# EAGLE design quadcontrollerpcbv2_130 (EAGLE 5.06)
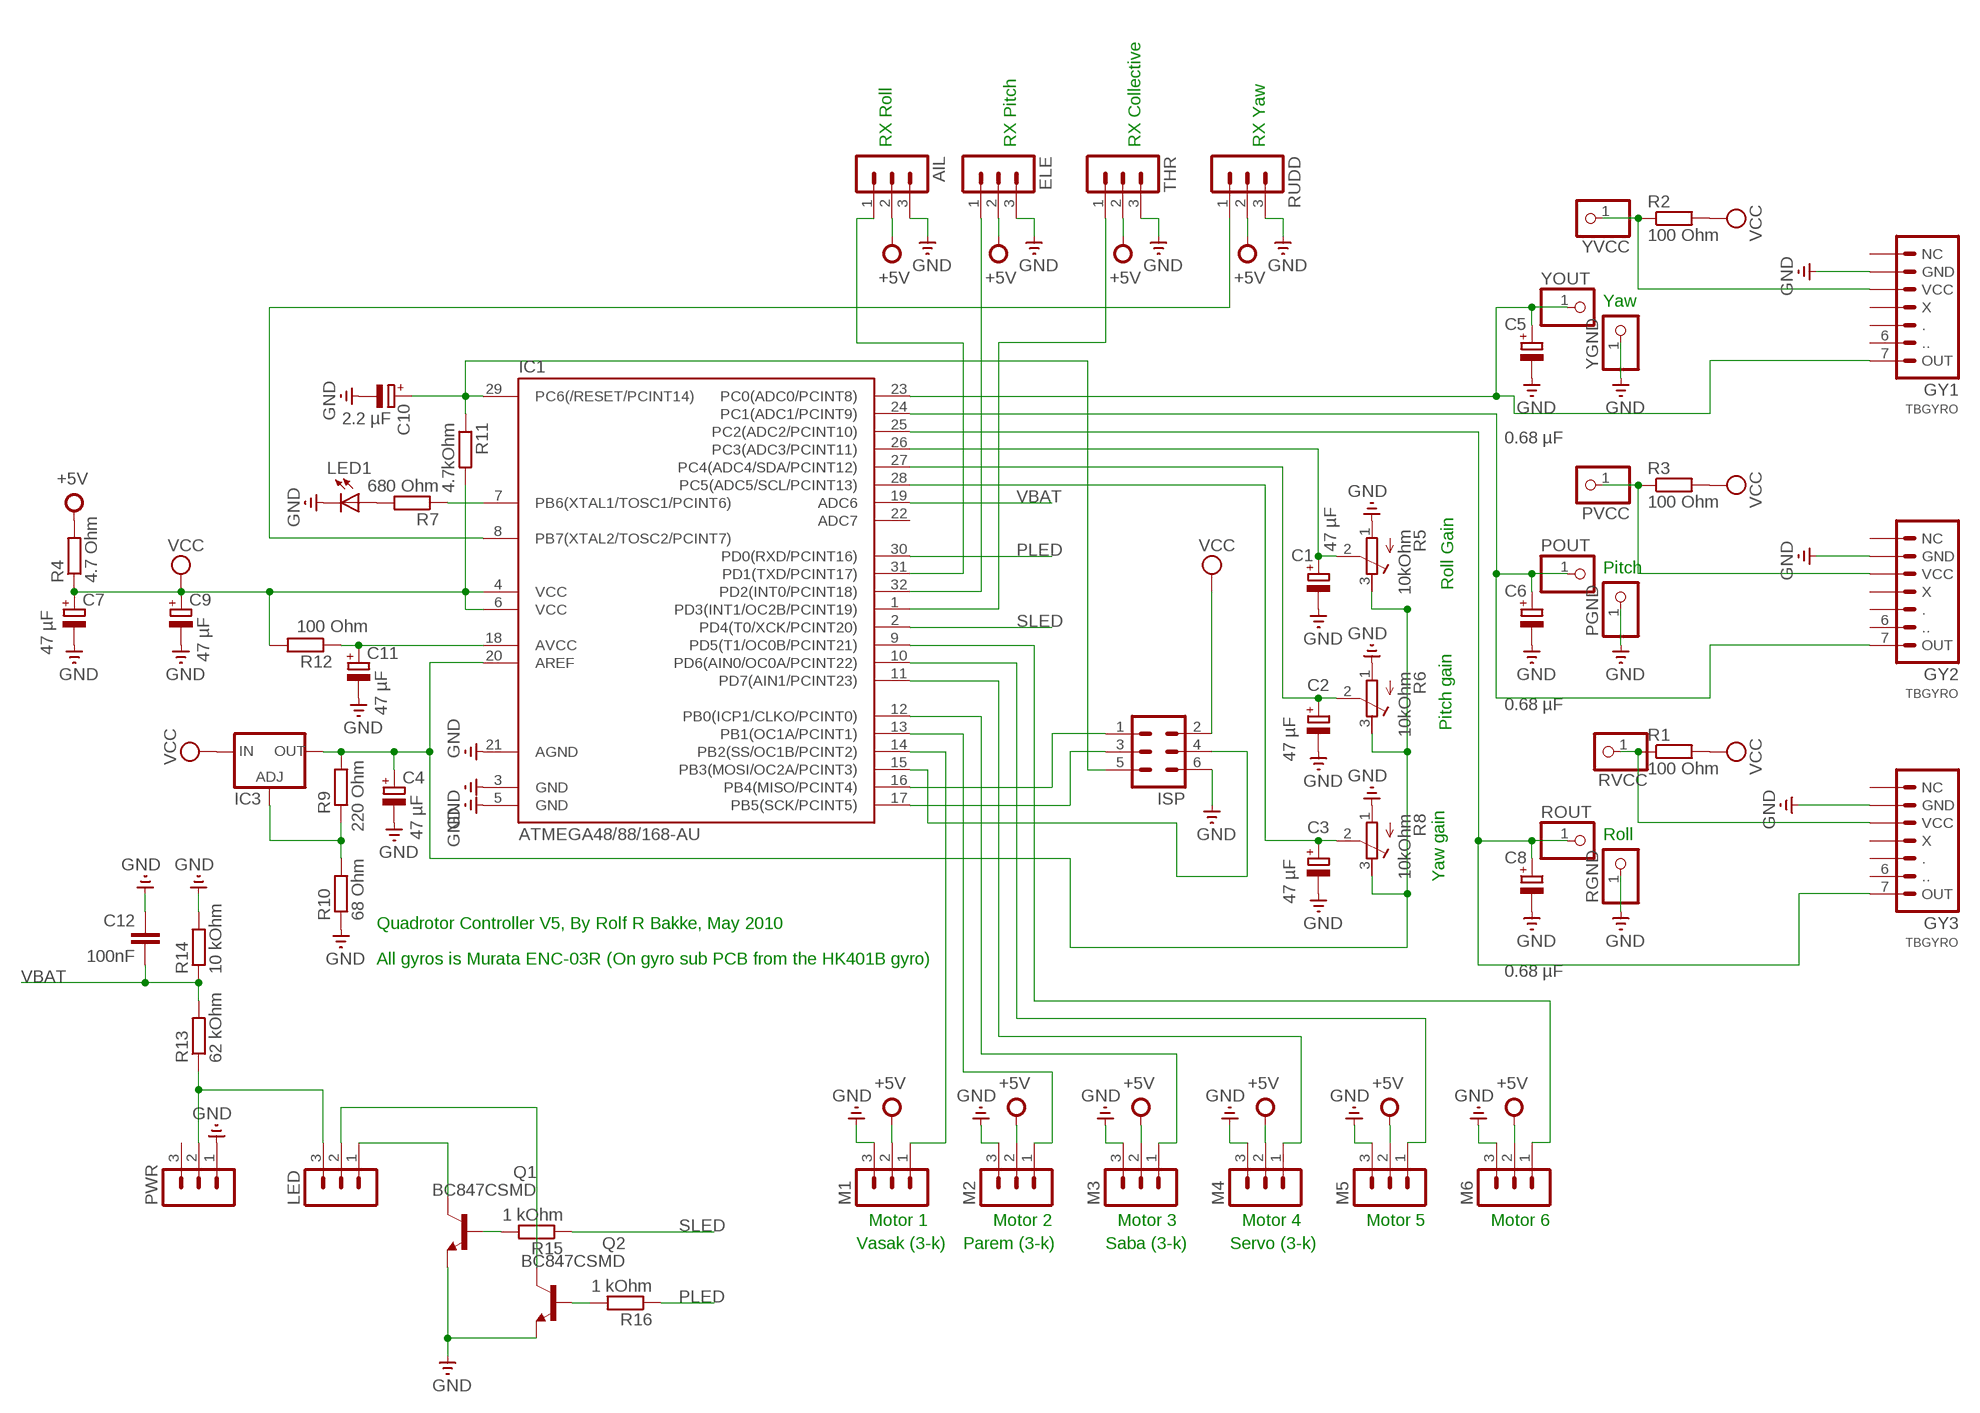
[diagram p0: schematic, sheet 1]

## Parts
AIL  MA03-1  [MA03-1]
C1  47 µF  CPOL-EUB/3528-21R  [B/3528-21R]
C2  47 µF  CPOL-EUB/3528-21R  [B/3528-21R]
C3  47 µF  CPOL-EUB/3528-21R  [B/3528-21R]
C4  47 µF  CPOL-EUB/3528-21R  [B/3528-21R]
C5  0.68 µF  CPOL-EUB/3528-21R  [B/3528-21R]
C6  0.68 µF  CPOL-EUB/3528-21R  [B/3528-21R]
C7  47 µF  CPOL-EUB/3528-21R  [B/3528-21R]
C8  0.68 µF  CPOL-EUB/3528-21R  [B/3528-21R]
C9  47 µF  CPOL-EUB/3528-21R  [B/3528-21R]
C10  2.2 µF  CPOL-EUB/3528-21R  [B/3528-21R]
C11  47 µF  CPOL-EUB/3528-21R  [B/3528-21R]
C12  100nF  C-EUC0603K  [C0603K]
ELE  MA03-1  [MA03-1]
GY1  TBGYRO  [TBGYRO]
GY2  TBGYRO  [TBGYRO]
GY3  TBGYRO  [TBGYRO]
IC1  ATMEGA48/88/168-AU  [TQFP32-08]
IC3  LM317LZ  [317L]
ISP  MA03-2  [MA03-2]
LED  MA03-1  [MA03-1]
LED1  LEDCHIPLED_0805  [CHIPLED_0805]
M1  MA03-1  [MA03-1]
M2  MA03-1  [MA03-1]
M3  MA03-1  [MA03-1]
M4  MA03-1  [MA03-1]
M5  MA03-1  [MA03-1]
M6  MA03-1  [MA03-1]
PGND  PINHD-1X1  [1X01]
POUT  PINHD-1X1  [1X01]
PVCC  PINHD-1X1  [1X01]
PWR  MA03-1  [MA03-1]
Q1  BC847CSMD  [SOT23]
Q2  BC847CSMD  [SOT23]
R1  100 Ohm  R-EU_R0805  [R0805]
R2  100 Ohm  R-EU_R0805  [R0805]
R3  100 Ohm  R-EU_R0805  [R0805]
R4  4.7 Ohm  R-EU_R0805  [R0805]
R5  10kOhm  R-TRIMM3314J  [RTRIM3314J]
R6  10kOhm  R-TRIMM3314J  [RTRIM3314J]
R7  680 Ohm  R-EU_R0805  [R0805]
R8  10kOhm  R-TRIMM3314J  [RTRIM3314J]
R9  220 Ohm  R-EU_R0805  [R0805]
R10  68 Ohm  R-EU_R0805  [R0805]
R11  4.7kOhm  R-EU_R0805  [R0805]
R12  100 Ohm  R-EU_R0805  [R0805]
R13  62 kOhm  R-EU_R0805  [R0805]
R14  10 kOhm  R-EU_R0805  [R0805]
R15  1 kOhm  R-EU_R0805  [R0805]
R16  1 kOhm  R-EU_R0805  [R0805]
RGND  PINHD-1X1  [1X01]
ROUT  PINHD-1X1  [1X01]
RUDD  MA03-1  [MA03-1]
RVCC  PINHD-1X1  [1X01]
THR  MA03-1  [MA03-1]
YGND  PINHD-1X1  [1X01]
YOUT  PINHD-1X1  [1X01]
YVCC  PINHD-1X1  [1X01]

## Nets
+5V: AIL.2 ELE.2 M1.2 M2.2 M3.2 M4.2 M5.2 M6.2 R4.2 RUDD.2 THR.2
GND: AIL.3 C1.- C2.- C3.- C4.- C5.- C6.- C7.- C8.- C9.- C10.- C11.- C12.1 ELE.3 GY1.2(GND) GY2.2(GND) GY3.2(GND) IC1.3(GND) IC1.5(GND) IC1.21(AGND) ISP.6 LED1.C M1.3 M2.3 M3.3 M4.3 M5.3 M6.3 PGND.1 PWR.1 Q1.2(E) Q2.2(E) R5.1(E) R6.1(E) R8.1(E) R10.1 R14.2 RGND.1 RUDD.3 THR.3 YGND.1
MISO: IC1.16(PB4(MISO/PCINT4)) ISP.1
MOSI: IC1.15(PB3(MOSI/OC2A/PCINT3)) ISP.4
N$1: C1.+ IC1.26(PC3(ADC3/PCINT11)) R5.2(S)
N$2: C2.+ IC1.27(PC4(ADC4/SDA/PCINT12)) R6.2(S)
N$3: C3.+ IC1.28(PC5(ADC5/SCL/PCINT13)) R8.2(S)
N$4: C4.+ IC1.20(AREF) IC3.2(OUT) R5.3(A) R6.3(A) R8.3(A) R9.2
N$5: LED1.A R7.2
N$6: IC3.1(ADJ) R9.1 R10.2
N$8: IC1.7(PB6(XTAL1/TOSC1/PCINT6)) R7.1
N$13: AIL.1 IC1.31(PD1(TXD/PCINT17))
N$14: ELE.1 IC1.32(PD2(INT0/PCINT18))
N$15: IC1.1(PD3(INT1/OC2B/PCINT19)) THR.1
N$16: IC1.8(PB7(XTAL2/TOSC2/PCINT7)) RUDD.1
N$17: IC1.14(PB2(SS/OC1B/PCINT2)) M1.1
N$18: IC1.13(PB1(OC1A/PCINT1)) M2.1
N$19: IC1.12(PB0(ICP1/CLKO/PCINT0)) M3.1
N$20: IC1.11(PD7(AIN1/PCINT23)) M4.1
N$21: C5.+ GY1.7(OUT) IC1.23(PC0(ADC0/PCINT8)) YOUT.1
N$22: GY1.3(VCC) R2.1 YVCC.1
N$23: GY2.3(VCC) PVCC.1 R3.1
N$24: C6.+ GY2.7(OUT) IC1.24(PC1(ADC1/PCINT9)) POUT.1
N$25: C8.+ GY3.7(OUT) IC1.25(PC2(ADC2/PCINT10)) ROUT.1
N$26: GY3.3(VCC) R1.1 RVCC.1
N$27: IC1.10(PD6(AIN0/OC0A/PCINT22)) M5.1
N$28: IC1.9(PD5(T1/OC0B/PCINT21)) M6.1
N$29: LED.3 PWR.2 R13.1
N$30: LED.1 Q1.3(C)
N$31: LED.2 Q2.3(C)
N$32: Q1.1(B) R15.2
N$33: C11.+ IC1.18(AVCC) R12.1
N$34: Q2.1(B) R16.2
PLED: IC1.30(PD0(RXD/PCINT16)) R16.1
RESET: C10.+ IC1.29(PC6(/RESET/PCINT14)) ISP.5 R11.1
SCK: IC1.17(PB5(SCK/PCINT5)) ISP.3
SLED: IC1.2(PD4(T0/XCK/PCINT20)) R15.1
VBAT: C12.2 IC1.19(ADC6) R13.2 R14.1
VCC: C7.+ C9.+ IC1.4(VCC) IC1.6(VCC) IC3.3(IN) ISP.2 R1.2 R2.2 R3.2 R4.1 R11.2 R12.2
Unconnected: GY1.1(NC) GY1.4(X) GY1.5(.) GY1.6(..) GY2.1(NC) GY2.4(X) GY2.5(.) GY2.6(..) GY3.1(NC) GY3.4(X) GY3.5(.) GY3.6(..) IC1.22(ADC7) PWR.3

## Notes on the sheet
- RX Roll | RX Pitch | RX Collective | RX Yaw
- Yaw
- Pitch
- Roll Gain
- Pitch gain
- Roll
- Yaw gain
- Quadrotor Controller V5, By Rolf R Bakke, May 2010
- All gyros is Murata ENC-03R (On gyro sub PCB from the HK401B gyro)
- Motor 1 | Motor 2 | Motor 3 | Motor 4 | Motor 5 | Motor 6
- Vasak (3-k) | Parem (3-k) | Saba (3-k) | Servo (3-k)

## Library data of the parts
AIL ELE LED M1-M6 PWR RUDD THR = con-lstb:MA03-1: PIN HEADER
C1-C11 = rcl:CPOL-EU: POLARIZED CAPACITOR, European symbol
C12 = rcl:C-EU: CAPACITOR, European symbol
GY1-GY3 = SparkFun:TBGYRO
IC1 = atmega8:ATMEGA48/88/168
IC3 = v-reg-3:LM317L: Adjustable Voltage Regulator, 1.2V to 37V, 100mA
ISP = con-lstb:MA03-2: PIN HEADER
LED1 = led:LED: LED
PGND POUT PVCC RGND ROUT RVCC YGND YOUT YVCC = pinhead:PINHD-1X1: PIN HEADER
Q1 Q2 = transistor-npn:BC847*: NPN Transistor
R1-R4 R7 R9-R16 = resistor:R-EU_: RESISTOR, European symbol
R5 R6 R8 = resistor:R-TRIMM: Trimm resistor

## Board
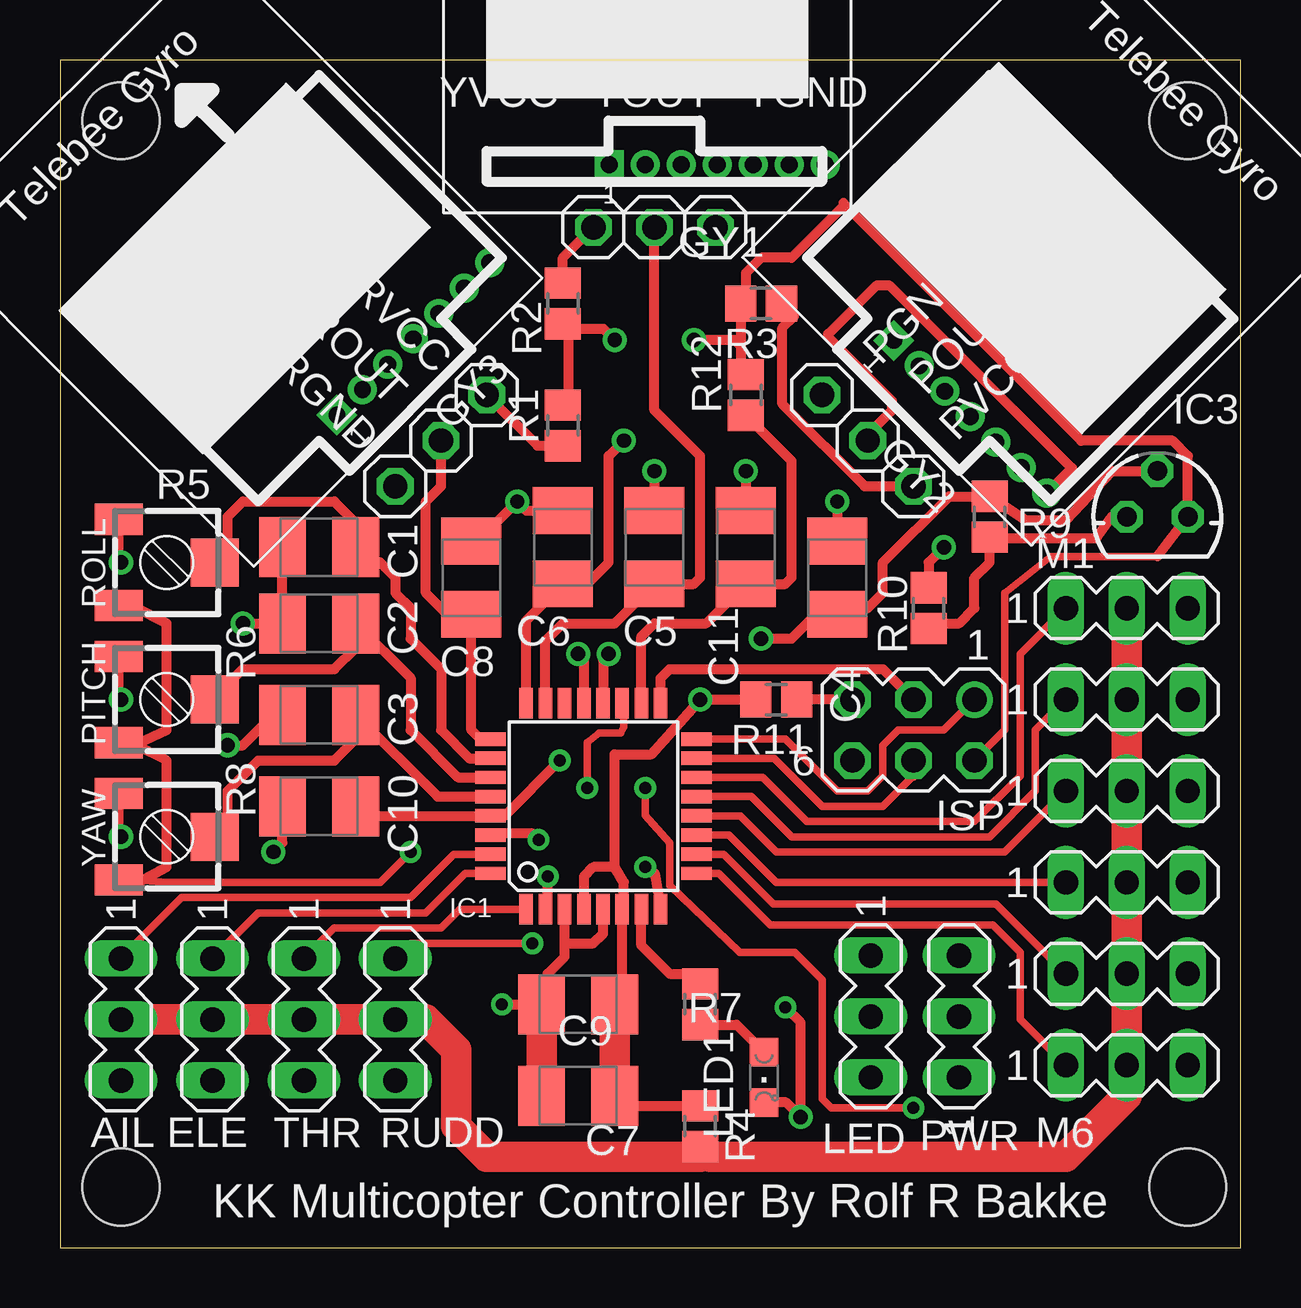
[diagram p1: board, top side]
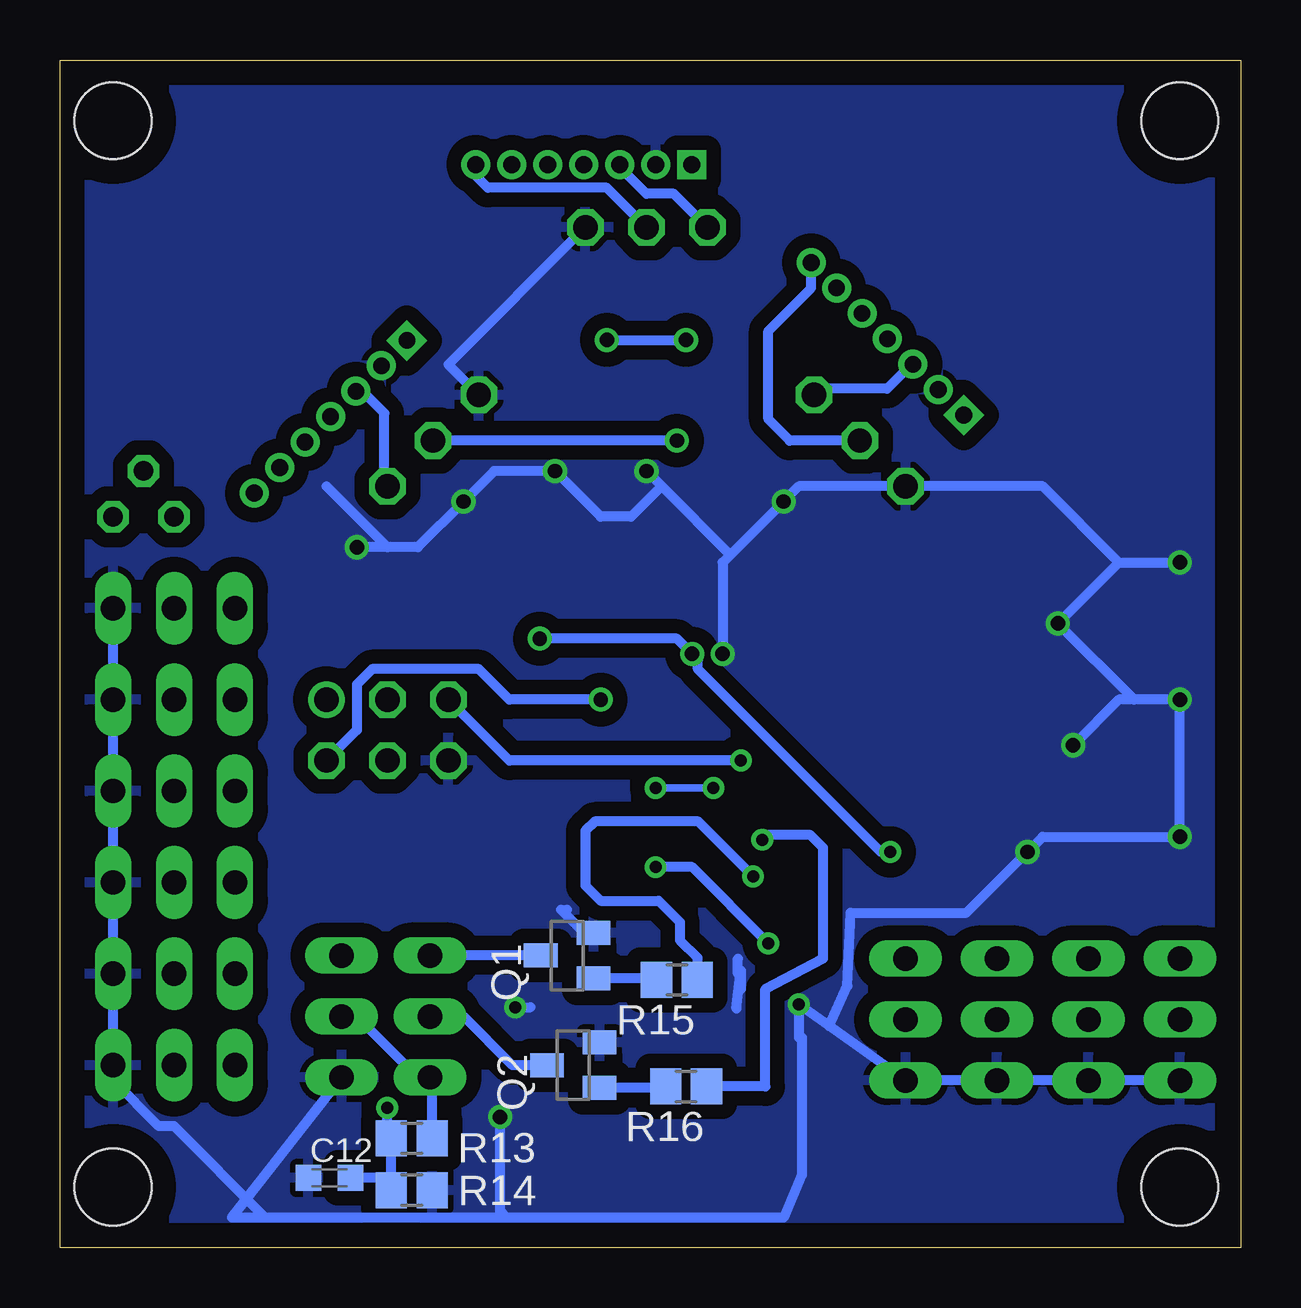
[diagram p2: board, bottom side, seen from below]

Size 49.2 x 49.52 mm. Coordinates in mm from the lower left corner, seen from the top.
Outline: 0,0 49.2,0 49.2,49.52 0,49.52 0,0
Copper layers (1*16): Top 0.035mm / dielectric 1.5mm / Bottom 0.035mm
Design rules "default *": minimum track width 10mil, minimum drill 20mil, track to track 8mil, track to pad 8mil, pad to pad 8mil, via to via 8mil, smd to smd 0mil, copper to edge 40mil, drill to drill 8mil, minimum pad ring 10mil, minimum via ring 8mil, stop-mask expansion 4mil, vias tented up to drill 0mil, thermal gap 10mil
Holes 3.2 mm at 2.54,46.99 46.99,46.99 46.99,2.54 2.54,2.54

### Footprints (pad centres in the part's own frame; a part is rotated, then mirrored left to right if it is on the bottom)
MA03-1 = drill 1.016 long: 1 -2.54,0; 2 0,0; 3 2.54,0
B/3528-21R = smd 1.95 x 2.5: + 1.525,0; - -1.525,0
C0603K = smd 1.05 x 1.08: 1 -0.875,0; 2 0.875,0
TBGYRO = drill 0.7 square: 1 -10.01,1.981 | drill 0.7 round: 2 -8.51,1.981; 3 -7.01,1.981; 4 -5.51,1.981; 5 -4.01,1.981; 6 -2.512,1.981; 7 -1.013,1.981
TQFP32-08 = smd 1.27 x 0.559: 1 -4.293,2.8; 2 -4.293,2; 3 -4.293,1.2; 4 -4.293,0.4; 5 -4.293,-0.4; 6 -4.293,-1.2; 7 -4.293,-2; 8 -4.293,-2.8; 17 4.293,-2.8; 18 4.293,-2; 19 4.293,-1.2; 20 4.293,-0.4; 21 4.293,0.4; 22 4.293,1.2; 23 4.293,2; 24 4.293,2.8 | smd 0.559 x 1.27: 9 -2.8,-4.293; 10 -2,-4.293; 11 -1.2,-4.293; 12 -0.4,-4.293; 13 0.4,-4.293; 14 1.2,-4.293; 15 2,-4.293; 16 2.8,-4.293; 25 2.8,4.293; 26 2,4.293; 27 1.2,4.293; 28 0.4,4.293; 29 -0.4,4.293; 30 -1.2,4.293; 31 -2,4.293; 32 -2.8,4.293
317L = drill 0.813 octagon: 1 -1.27,0; 2 0,1.905; 3 1.27,0
MA03-2 = drill 1.016 round: 1 -2.54,-1.27 | drill 1.016 octagon: 2 -2.54,1.27; 3 0,-1.27; 4 0,1.27; 5 2.54,-1.27; 6 2.54,1.27
CHIPLED_0805 = smd 1.2 x 1.2: A 0,-1.05; C 0,1.05
1X01 = drill 1.016 octagon: 1 0,0
SOT23 = smd 1 x 1.4: 1 -0.95,-1.1; 2 0.95,-1.1; 3 0,1.1
R0805 = smd 1.3 x 1.5: 1 -0.85,0; 2 0.85,0
RTRIM3314J = smd 1.3 x 2: 1 -1.8,-2; 3 1.8,-2 | smd 2 x 2: 2 0,2

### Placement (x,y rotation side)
AIL  2.54,9.53 270 top
C1  10.79,29.21 0 top
C2  10.79,26.04 0 top
C3  10.79,22.23 0 top
C4  32.38,27.94 270 top
C5  24.77,29.21 270 top
C6  20.95,29.21 270 top
C7  21.59,6.35 0 top
C8  17.14,27.94 270 top
C9  21.59,10.16 0 top
C10  10.79,18.41 0 top
C11  28.57,29.21 270 top
C12  37.97,2.92 0 bottom
ELE  6.35,9.53 270 top
GY1  32.89,43.18 0 top
GY2  40.42,29.35 315 top
GY3  20.02,40.39 45 top
IC1  22.23,18.41 90 top
IC3  45.72,30.48 0 top
ISP  35.56,21.59 180 top
LED  33.78,9.65 270 top
LED1  29.34,7.11 180 top
M1  44.45,26.67 0 top
M2  44.45,22.86 0 top
M3  44.45,19.05 0 top
M4  44.45,15.24 0 top
M5  44.45,11.43 0 top
M6  44.45,7.62 0 top
PGND  31.75,35.56 0 top
POUT  33.66,33.66 0 top
PVCC  35.56,31.75 0 top
PWR  37.47,9.65 90 top
Q1  28.07,12.19 90 bottom
Q2  27.81,7.62 90 bottom
R1  20.95,34.29 90 top
R2  20.95,39.37 270 top
R3  29.21,39.37 180 top
R4  26.67,5.08 270 top
R5  4.45,28.57 270 top
R6  4.45,22.86 270 top
R7  26.67,10.16 270 top
R8  4.45,17.14 270 top
R9  38.73,30.48 90 top
R10  36.2,26.67 270 top
R11  29.84,22.86 180 top
R12  28.57,35.56 90 top
R13  34.54,4.57 180 bottom
R14  34.54,2.41 0 bottom
R15  23.5,11.18 180 bottom
R16  23.11,6.73 180 bottom
RGND  13.97,31.75 0 top
ROUT  15.88,33.66 0 top
RUDD  13.97,9.53 270 top
RVCC  17.78,35.56 0 top
THR  10.16,9.53 270 top
YGND  27.3,42.55 0 top
YOUT  24.77,42.55 0 top
YVCC  22.23,42.55 0 top

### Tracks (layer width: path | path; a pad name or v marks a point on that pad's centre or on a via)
+5V
  Top 1.27: M1.2 M2.2 M3.2 M4.2 M5.2 M6.2 44.45,6.35 41.91,3.81 27.09,3.81 R4.2 26.67,3.81 17.78,3.81 16.51,5.08 16.51,8.26 15.24,9.53 RUDD.2 THR.2 ELE.2 AIL.2
GND  (via drill 0.5, 0.6)
  Top 0.406: v18.41,10.16 C9.- 20.32,10.41 20.32,11.43 21.02,12.13 21.02,12.7 | IC1.21 21.82,24.53 v21.59,24.77 | v24.77,32.38 C5.- | R10.1 36.2,28.57 v36.83,29.21 | C6.- 19.43,30.73 v19.05,31.11 17.4,29.46 C8.- | v7.62,26.04 C2.- C1.- | C3.- 8.89,22.23 7.62,20.95 v6.99,20.95 | C10.- 9.27,16.89 v8.89,16.51 | R5.1 2.44,28.67 v2.54,28.57 | R6.1 2.44,22.95 v2.54,22.86 | R8.1 2.44,17.24 v2.54,17.14 | v32.38,31.11 C4.- | v28.57,32.38 C11.- | 21.02,12.7 IC1.3 | IC1.5 22.62,13.1 22.23,12.7 21.02,12.7 | LED1.C 30.26,6.06 v30.86,5.46 30.86,9.4 v30.23,10.03
  Top 1.27: C9.- C7.-
  Bottom 0.406: AIL.3 ELE.3 THR.3 RUDD.3 17.15,9.26 | 17.15,9.26 v18.41,10.16 18.41,8.76 18.29,8.76 18.29,3.05 19.05,1.27 30.61,1.27 | 30.61,1.27 37.34,1.27 | 37.34,1.27 40.64,1.27 44.45,5.08 45.09,5.08 46.99,6.99 M6.3 M5.3 M4.3 M3.3 M2.3 M1.3 | 20.83,11.56 20.83,10.79 | 20.83,11.56 20.95,11.43 20.95,12.06 | 21.02,9.97 20.83,11.56 | 17.15,9.26 16.39,10.92 16.26,13.97 11.43,13.97 v8.89,16.51 8.26,17.14 v2.54,17.14 v2.54,22.86 | v2.54,22.86 5.08,22.86 v6.99,20.95 | v2.54,22.86 4.45,22.86 v7.62,26.04 5.08,28.57 | 5.08,28.57 v2.54,28.57 | 5.08,28.57 8.26,31.75 RGND.1 18.41,31.75 v19.05,31.11 21.27,28.89 | v21.59,24.77 21.59,28.57 21.27,28.89 | 21.27,28.89 24.13,31.75 | 24.13,31.75 v24.77,32.38 | 24.13,31.75 25.4,30.48 26.67,30.48 v28.57,32.38 31.11,32.38 v32.38,31.11 34.29,29.21 35.56,29.21 | 35.56,29.21 v36.83,29.21 | 35.56,29.21 38.1,31.75 | PGND.1 33.02,36.83 YGND.1 | PWR.1 42.04,1.27 37.34,1.27 | v30.86,5.46 30.86,1.52 30.61,1.27 | Q1.2 27.37,13.14 28.32,14.1 28.07,14.1 | v30.23,10.03 29.59,10.03
  pour Bottom (isolate 0.61): 1.27,1.27 1.27,48.26 48.26,48.26 48.26,1.27
MISO
  Top 0.305: IC1.16 30.22,21.21 32.38,19.05 33.66,19.05 34.29,19.68 34.29,20.95 34.92,21.59 36.83,21.59 ISP.1
MOSI
  Top 0.305: IC1.15 29.75,20.41 31.75,18.41 34.29,18.41 35.56,19.68
  Top 0.406: 35.56,19.68 ISP.4
N$1
  Top 0.406: IC1.26 17.05,20.41 15.88,21.59 15.88,24.13 14.61,25.4 14.61,26.67 13.97,27.3 13.97,27.94 13.34,28.57 12.96,28.57 C1.+ 12.32,30.23 11.43,31.11 7.62,31.11 6.99,30.48 6.99,29.11 R5.2
N$2
  Top 0.406: 7.08,22.23 R6.2 6.99,23.4 6.99,23.5 7.62,24.13 11.43,24.13 12.32,25.02 C2.+ 14.61,23.75 14.61,21.59 16.58,19.61 IC1.27
N$3
  Top 0.406: IC1.28 15.73,18.82 C3.+ 12.32,21.21 11.43,20.32 8.26,20.32 6.99,19.05 6.99,17.68 R8.2
N$4  (via drill 0.5, 0.6)
  Top 0.305: 3.28,15.35 4.45,15.24 13.34,15.24 v14.61,16.51
  Top 0.406: 3.28,15.35 R8.3 3.08,15.14 4.45,15.88 4.45,20.32 3.17,20.95 2.55,20.95 R6.3 3.28,21.06 4.45,21.59 4.45,26.04 3.17,26.67 2.55,26.67 R5.3 | IC1.20 22.62,24.53 v22.86,24.77 | v29.21,25.4 30.48,25.4 31.5,26.41 C4.+ 32.64,26.67 33.66,26.67 34.29,27.3 34.29,28.57 37.05,31.33 R9.2 | IC3.2 43.81,32.38 41.91,30.35 40.22,30.35 R9.2 | R9.2 38.95,31.11
  Bottom 0.406: v14.61,16.51 15.01,16.51 22.62,24.13 22.62,24.53 v22.86,24.77 23.5,25.4 v29.21,25.4
N$5
  Top 0.406: R7.2 28.19,9.31 LED1.A
N$6
  Top 0.406: IC3.1 43.81,30.48 43.18,29.59 38.95,29.59 R9.1 38.73,28.57 38.1,27.94 38.1,26.67 37.47,26.04 36.41,26.04 R10.2
N$8
  Top 0.406: IC1.7 24.23,12.61 25.4,11.43 26.25,11.43 R7.1
N$13
  Top 0.305: IC1.31 16.41,16.41 14.61,14.61 5.08,14.61 AIL.1
N$14
  Top 0.305: IC1.32 16.89,15.62 15.24,13.97 8.26,13.97 ELE.1
N$15
  Top 0.305: IC1.1 16.66,14.12 15.88,13.34 11.43,13.34 THR.1
N$16  (via drill 0.5)
  Top 0.305: v19.68,12.7 14.61,12.7 RUDD.1
  Top 0.406: IC1.8 24.77,15.62 v24.38,15.88
  Bottom 0.406: v19.68,12.7 22.86,15.88 v24.38,15.88
N$17
  Top 0.305: IC1.14 29.28,19.61 31.11,17.78 38.1,17.78 40.01,19.68 40.01,24.77 M1.1
N$18
  Top 0.305: IC1.13 28.81,18.82 30.48,17.14 38.73,17.14 40.64,19.05 40.64,21.59 M2.1
N$19
  Top 0.305: IC1.12 28.34,18.02 29.84,16.51 39.37,16.51 M3.1
N$20
  Top 0.305: IC1.11 27.87,17.21 29.84,15.24 M4.1
N$21
  Top 0.406: IC1.23 20.23,25.3 20.95,26.04 23.11,26.04 C5.+ 26.41,27.68 26.67,27.94 26.67,33.02 24.77,34.92 YOUT.1
  Bottom 0.406: GY1.7 31.88,44.71 31.37,44.2 26.42,44.2 YOUT.1
N$22
  Top 0.406: R2.1 20.95,41.27 YVCC.1
  Bottom 0.406: GY1.3 25.88,45.06 24.77,43.94 23.62,43.94 YVCC.1
N$23
  Top 0.406: R3.1 30.59,38.84 30.1,38.35 30.1,35.18 33.53,31.75 PVCC.1
  Bottom 0.406: GY2.3 36.6,35.71 35.69,34.8 35.69,31.88 PVCC.1
N$24  (via drill 0.6)
  Top 0.406: IC1.24 19.43,26.16 C6.+ 21.97,27.68 22.86,28.57 22.86,33.02 v23.5,33.66 | POUT.1 33.66,33.91 34.67,34.92 34.67,35.31 32,37.97 32,38.1 34.04,40.13 34.54,40.13 42.16,32.51 42.15,32.51 GY2.7
  Bottom 0.406: v23.5,33.66 POUT.1
N$25
  Top 0.406: IC1.25 17.52,21.21 17.14,21.59 C8.+ 16.13,26.41 15.24,27.3 15.24,31.11 15.88,31.75 ROUT.1 15.75,33.53
  Bottom 0.406: GY3.7 17.9,40.01 19.68,38.23 19.68,34.54 18.8,33.66 ROUT.1
N$26
  Top 0.406: R1.1 19.9,33.44 RVCC.1
  Bottom 0.406: 17.62,35.4 RVCC.1 17.53,35.81 14.73,35.81 13.71,36.84 GY3.3
N$27
  Top 0.305: IC1.10 27.65,16.41 29.72,14.35 38.99,14.35 M5.1
N$28
  Top 0.305: IC1.9 27.44,15.62 29.59,13.46 38.86,13.46 40.01,12.32 40.01,9.53 M6.1
N$29
  Bottom 0.406: PWR.2 36.83,9.65 34.29,7.11 LED.3 33.69,7.02 R13.1
N$30
  Bottom 0.406: Q1.3 LED.1
N$31
  Bottom 0.406: Q2.3 30.35,7.62 32.38,9.65 LED.2
N$32
  Bottom 0.406: Q1.1 24.41,11.24 R15.2
N$33
  Top 0.406: IC1.18 24.23,25.5 24.77,26.04 26.93,26.04 C11.+ 30.23,27.68 30.48,27.94 30.48,32.8 R12.1
N$34
  Bottom 0.406: Q2.1 24.02,6.67 R16.2
PLED  (via drill 0.5)
  Top 0.406: v19.94,17.02 19.68,17.27 17.99,17.27 IC1.30
  Bottom 0.406: R16.1 19.81,6.73 19.81,10.79 17.4,12.06 17.4,16.68 IC1.30 19.74,17.21 v19.94,17.02
RESET  (via drill 0.5)
  Top 0.406: v20.83,20.32 18.52,18.02 IC1.29 12.72,18.02 C10.+ | ISP.5 R11.1
  Bottom 0.406: v20.83,20.32 30.48,20.32 ISP.5
SCK
  Top 0.406: IC1.17 25.02,23.75 25.4,24.13 34.29,24.13 ISP.3
SLED  (via drill 0.5)
  Top 0.406: v20.32,15.49 20.32,14.22 IC1.2
  Bottom 0.406: R15.1 22.64,12.1 23.37,12.83 23.37,13.59 24.26,14.48 26.67,14.48 27.3,15.11 27.3,17.4 26.92,17.78 22.61,17.78 v20.32,15.49
VBAT  (via drill 0.5)
  Top 0.305: v35.56,5.84 32.13,5.84 31.75,6.22 31.75,11.18 30.61,12.32 28.32,12.32 25.4,15.11 25.4,16.89 24.38,18.03 v24.38,19.18 | v21.97,19.18 21.97,21.08 22.48,21.46 23.37,21.46 23.5,21.72 23.5,22.64 IC1.19
  Bottom 0.305: v24.38,19.18 v21.97,19.18
  Bottom 0.406: C12.2 35.9,2.92 R14.1 R13.2 35.56,4.57 v35.56,5.84
VCC  (via drill 0.6)
  Top 0.305: ISP.2 39.37,21.59 39.37,27.3 41.27,28.83 45.72,28.83
  Top 0.406: IC1.4 21.82,15.47 22.23,15.88 23.11,15.88 | 23.11,15.88 23.5,15.24 23.5,14.12 IC1.6 23.43,10.16 C9.+ | R4.1 23.54,5.93 C7.+ | R1.2 21.17,34.92 21.17,38.3 | 23.11,15.88 23.11,20.57 24.64,20.57 v26.67,22.86 R11.2 | 45.72,28.83 IC3.3 46.99,33.02 46.35,33.66 42.55,33.66 32.64,43.56 32.64,43.43 30.48,41.27 29.21,41.27 28.57,40.64 28.57,39.59 R3.2 28.36,37.59 | 21.17,38.3 R2.2 | 28.36,37.59 28.36,36.62 R12.2 | 21.17,38.3 22.66,38.3 v23.11,37.85 | v26.42,37.85 28.11,37.85 28.36,37.59
  Top 1.27: C7.+ C9.+
  Bottom 0.406: v26.67,22.86 30.48,22.86 31.75,24.13 36.2,24.13 36.83,23.5 36.83,21.59 ISP.2 | v26.42,37.85 v23.11,37.85

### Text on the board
tNames: Pitch | Roll | ROLL | PITCH | YAW | KK Multicopter Controller By Rolf R Bakke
